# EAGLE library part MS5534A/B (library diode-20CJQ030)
Intersema Sensoric SA MS5534B (RoHS*) BAROMETER MODULE DESCRIPTION: The MS5534B is a SMD-hybrid device including a piezoresistive pressure sensor and an ADC-Interface IC. It provides a 16 Bit data word from a pressure and temperature dependent voltage. Additionally the module contains 6 readable coefficients for a highly accurate software calibration of the sensor. MS5534B is a low power, low voltage device with automatic power down (ON/OFF) switching. A 3-wire interface is used for all communications with a microcontroller. Sensor packaging options are plastic or metal cap. Compared to the previous version (MS5534A) the temperature range has been improved (-40 to +125°C) as well as the pressure range (measurement down to 10 mbar). Other improvements concern the ESD sensitivity, current consumption and converter accuracy. FEATURES: Supply voltage 2.2 V to 3.6 V Low supply current -40°C to +125°C operation temperature No external components required 10 - 1100 mbar absolute pressure range 6 coefficients for software compensation storedon-chip Piezoresistive silicon micromachined sensor Integrated miniature pressure sensor 9 x 9 mm 15 Bit ADC 3-wire serial interface 1 system clock line (32.768 kHz) Low voltage and low power consumption RoHS-compatible & Pb-free* APPLICATIONS Mobile altimeter / barometer systems Weather control systems Adventure or multi-mode watches GPS receivers Please send any comments to: messi@users.sourceforge.net
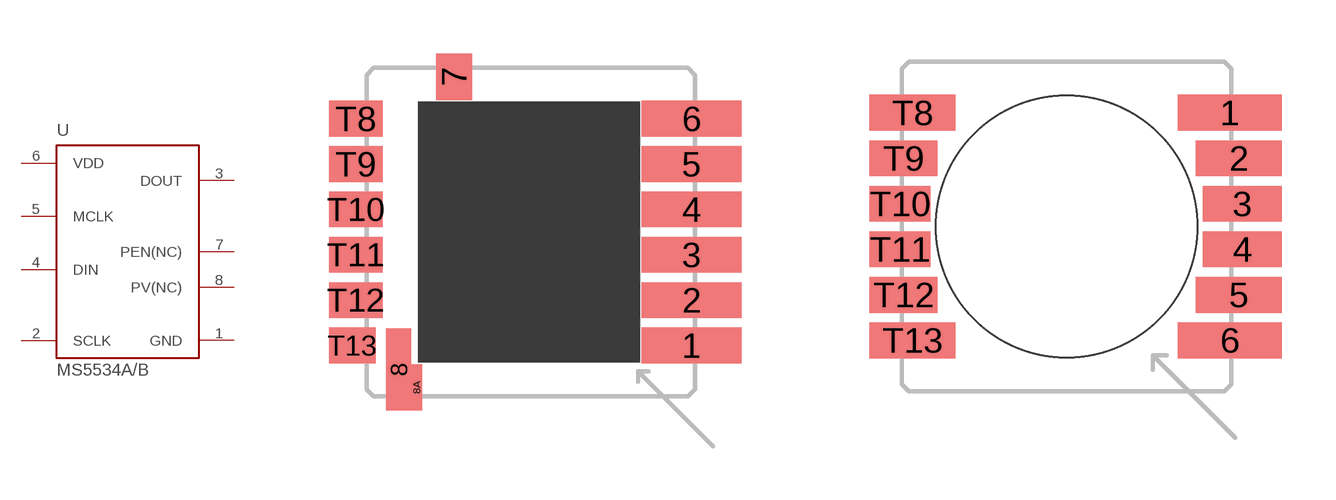
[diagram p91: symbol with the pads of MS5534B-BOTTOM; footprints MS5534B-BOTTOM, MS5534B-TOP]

Designator prefix U

## MS5534A/B-BOTTOM  [MS5534B-BOTTOM]
1  GND  pwr
2  SCLK  in
3  DOUT  out
4  DIN  in
5  MCLK  in
6  VDD  pwr
7  PEN(NC)  nc
8  PV(NC)  nc

## MS5534A/B-TOP  [MS5534B-TOP]
1  GND  pwr
2  SCLK  in
3  DOUT  out
4  DIN  in
5  MCLK  in
6  VDD  pwr
T8  PEN(NC)  nc
T9  PV(NC)  nc

## Footprint MS5534B-BOTTOM (pad centres in mm)
Pad layout for bottom side of MS5534B soldered onto printed circuit board
smd 2.8 x 1: 1 4.5,-3.175; 2 4.5,-1.905; 3 4.5,-0.635; 4 4.5,0.635; 5 4.5,1.905; 6 4.5,3.175
smd 1 x 1.3: 7 -2.15,4.35
smd 0.7 x 2.3: 8 -3.7,-3.85
smd 0.3 x 1.3: 8A -3.2,-4.35
smd 1.5 x 1: T8 -4.9,3.175; T9 -4.9,1.905; T10 -4.9,0.635; T11 -4.9,-0.635; T12 -4.9,-1.905
smd 1.3 x 1: T13 -5,-3.175

## Footprint MS5534B-TOP (pad centres in mm)
Pad layout for top side of MS5534B soldered onto printed circuit board
smd 2.9 x 1: 1 4.55,3.175; 6 4.55,-3.175
smd 2.4 x 1: 2 4.8,1.905; 5 4.8,-1.905; T8 -4.3,3.175; T13 -4.3,-3.175
smd 2.2 x 1: 3 4.9,0.635; 4 4.9,-0.635
smd 1.9 x 1: T9 -4.55,1.905; T12 -4.55,-1.905
smd 1.7 x 1: T10 -4.65,0.635; T11 -4.65,-0.635
hole 7.3 at 0,0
